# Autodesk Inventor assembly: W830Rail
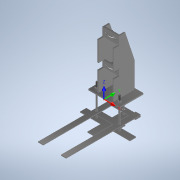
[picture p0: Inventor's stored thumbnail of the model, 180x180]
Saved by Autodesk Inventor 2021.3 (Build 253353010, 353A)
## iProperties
Created: 2019-06
Part Number: W830Rail
Document SubType Name: Assembly
Designer: u1426
Author: u1426
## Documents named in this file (10)
- S:\Projects\Billings\4889_STPP-14-3-17-78_WHEATLND-CO-L-EAST\BR\CSK_CADD-SKETCHES\Inventor_TJB\Parts\W830Post-Slab.iam
- S:\Projects\Billings\4889_STPP-14-3-17-78_WHEATLND-CO-L-EAST\BR\CSK_CADD-SKETCHES\Inventor_TJB\Parts\Post.ipt
- S:\Projects\Billings\4889_STPP-14-3-17-78_WHEATLND-CO-L-EAST\BR\CSK_CADD-SKETCHES\Inventor_TJB\Parts\ANSI B18.2.1 - 3_4-10 UNC - 1.25(4).ipt
- S:\Projects\Billings\4889_STPP-14-3-17-78_WHEATLND-CO-L-EAST\BR\CSK_CADD-SKETCHES\Inventor_TJB\Parts\ANSI B18.22.1 - 3_4 - wide - Type A.ipt
- S:\Projects\Billings\4889_STPP-14-3-17-78_WHEATLND-CO-L-EAST\BR\CSK_CADD-SKETCHES\Inventor_TJB\Parts\ANSI B18.2.2 - 3_4 - 10(8).ipt
- S:\Projects\Billings\4889_STPP-14-3-17-78_WHEATLND-CO-L-EAST\BR\CSK_CADD-SKETCHES\Inventor_TJB\Parts\RailBolt.ipt
- S:\Projects\Billings\4889_STPP-14-3-17-78_WHEATLND-CO-L-EAST\BR\CSK_CADD-SKETCHES\Inventor_TJB\Parts\ASME B18.21.1 - 5_8(1).ipt
- S:\Projects\Billings\4889_STPP-14-3-17-78_WHEATLND-CO-L-EAST\BR\CSK_CADD-SKETCHES\Inventor_TJB\Parts\ANSI B18.2.2 - 5_8 - 11(8).ipt
- S:\Projects\Billings\4889_STPP-14-3-17-78_WHEATLND-CO-L-EAST\BR\CSK_CADD-SKETCHES\Inventor_TJB\Parts\LowerAnchorage.ipt
- S:\Projects\Billings\4889_STPP-14-3-17-78_WHEATLND-CO-L-EAST\BR\CSK_CADD-SKETCHES\Inventor_TJB\Parts\UpperAnchorage.ipt
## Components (28 placed, 9 different names)
1. Post:1 — Flush:104, Flush:105, Flush:106, Flush:107, Flush:108, Flush:109, Flush:113, Flush:114, Flush:115, Flush:116, Mate:2, Flush:117, Mate:4, Flush:118, Mate:6, Mate:7, Mate:8, Mate:12, Mate:13, Mate:17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
2. LowerAnchorage:1 — Flush:107, Flush:108, Flush:109, Mate:1, Mate:3, Mate:5
3. UpperAnchorage:1 — Flush:104, Flush:105, Flush:106
4. Heavy Hex Bolt - Inch 3/4-10 UNC - 1.25:1 — Mate:1, Flush:116, Mate:2, Mate:9, Mate:10, Mate:11, Flush:119, Mate:24, Flush:122, Mate:25, Mate:26
5. Heavy Hex Bolt - Inch 3/4-10 UNC - 1.25:2 — Mate:3, Flush:117, Mate:4, Mate:14, Mate:15, Mate:16, Flush:120, Mate:29, Mate:30, Mate:31, Flush:123
6. Heavy Hex Bolt - Inch 3/4-10 UNC - 1.25:3 — Mate:5, Flush:118, Mate:6, Mate:19, Mate:20, Mate:21, Flush:121, Mate:34, Mate:35, Mate:36, Flush:124
7. Plain Washer (Inch) 3/4 - wide - Type A:1 — Mate:7, Mate:9, Mate:10, Mate:22
8. Plain Washer (Inch) 3/4 - wide - Type A:2 — Mate:8, Mate:11, Flush:119, Mate:23
9. Plain Washer (Inch) 3/4 - wide - Type A:3 — Mate:12, Mate:14, Mate:15, Mate:27
10. Plain Washer (Inch) 3/4 - wide - Type A:4 — Mate:13, Mate:16, Flush:120, Mate:28
11. Plain Washer (Inch) 3/4 - wide - Type A:5 — Mate:17, Mate:19, Mate:20, Mate:32
12. Plain Washer (Inch) 3/4 - wide - Type A:6 — Mate:18, Mate:21, Flush:121, Mate:33
13. Heavy Hex Nut - Inch 3/4 - 10:1 — Mate:22, Mate:24, Flush:122
14. Heavy Hex Nut - Inch 3/4 - 10:2 — Mate:23, Mate:25, Mate:26
15. Heavy Hex Nut - Inch 3/4 - 10:3 — Mate:27, Mate:29, Mate:30
16. Heavy Hex Nut - Inch 3/4 - 10:4 — Mate:28, Mate:31, Flush:123
17. Heavy Hex Nut - Inch 3/4 - 10:5 — Mate:32, Mate:34, Mate:35
18. Heavy Hex Nut - Inch 3/4 - 10:6 — Mate:33, Mate:36, Flush:124
19. RailBolt:1 — Mate:37, Mate:39, Flush:125, Mate:41, Mate:42, Mate:45, Flush:127, Mate:46, Flush:128, Mate:53, Flush:131, Mate:54, Flush:132
20. RailBolt:2 — Mate:38, Mate:40, Flush:126, Mate:43, Mate:44, Mate:47, Flush:129, Mate:48, Flush:130, Mate:55, Flush:133, Mate:56, Flush:134
21. Heavy Helical Spring Lock Washer (Inch) 5/8:1 — Mate:41, Mate:45, Flush:127, Mate:49
22. Heavy Helical Spring Lock Washer (Inch) 5/8:2 — Mate:42, Mate:46, Flush:128, Mate:50
23. Heavy Helical Spring Lock Washer (Inch) 5/8:3 — Mate:43, Mate:47, Flush:129, Mate:51
24. Heavy Helical Spring Lock Washer (Inch) 5/8:4 — Mate:44, Mate:48, Flush:130, Mate:52
25. Heavy Hex Nut - Inch 5/8 - 11:1 — Mate:49, Mate:53, Flush:131
26. Heavy Hex Nut - Inch 5/8 - 11:2 — Mate:50, Mate:54, Flush:132
27. Heavy Hex Nut - Inch 5/8 - 11:3 — Mate:51, Mate:55, Flush:133
28. Heavy Hex Nut - Inch 5/8 - 11:4 — Mate:52, Mate:56, Flush:134
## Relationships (84: Mate 56, Flush 28)
- Flush:104: Post:1 ↔ UpperAnchorage:1
- Flush:105: Post:1 ↔ UpperAnchorage:1
- Flush:106: Post:1 ↔ UpperAnchorage:1
- Flush:107: Post:1 ↔ LowerAnchorage:1
- Flush:108: Post:1 ↔ LowerAnchorage:1
- Flush:109: Post:1 ↔ LowerAnchorage:1
- Flush:113: Post:1
- Flush:114: Post:1
- Flush:115: Post:1
- Mate:1: LowerAnchorage:1 ↔ Heavy Hex Bolt - Inch 3/4-10 UNC - 1.25:1
- Flush:116: Post:1 ↔ Heavy Hex Bolt - Inch 3/4-10 UNC - 1.25:1
- Mate:2: Post:1 ↔ Heavy Hex Bolt - Inch 3/4-10 UNC - 1.25:1
- Mate:3: LowerAnchorage:1 ↔ Heavy Hex Bolt - Inch 3/4-10 UNC - 1.25:2
- Flush:117: Post:1 ↔ Heavy Hex Bolt - Inch 3/4-10 UNC - 1.25:2
- Mate:4: Post:1 ↔ Heavy Hex Bolt - Inch 3/4-10 UNC - 1.25:2
- Mate:5: LowerAnchorage:1 ↔ Heavy Hex Bolt - Inch 3/4-10 UNC - 1.25:3
- Flush:118: Post:1 ↔ Heavy Hex Bolt - Inch 3/4-10 UNC - 1.25:3
- Mate:6: Post:1 ↔ Heavy Hex Bolt - Inch 3/4-10 UNC - 1.25:3
- Mate:7: Post:1 ↔ Plain Washer (Inch) 3/4 - wide - Type A:1
- Mate:8: Post:1 ↔ Plain Washer (Inch) 3/4 - wide - Type A:2
- Mate:9: Heavy Hex Bolt - Inch 3/4-10 UNC - 1.25:1 ↔ Plain Washer (Inch) 3/4 - wide - Type A:1
- Mate:10: Heavy Hex Bolt - Inch 3/4-10 UNC - 1.25:1 ↔ Plain Washer (Inch) 3/4 - wide - Type A:1
- Mate:11: Heavy Hex Bolt - Inch 3/4-10 UNC - 1.25:1 ↔ Plain Washer (Inch) 3/4 - wide - Type A:2
- Flush:119: Heavy Hex Bolt - Inch 3/4-10 UNC - 1.25:1 ↔ Plain Washer (Inch) 3/4 - wide - Type A:2
- Mate:12: Post:1 ↔ Plain Washer (Inch) 3/4 - wide - Type A:3
- Mate:13: Post:1 ↔ Plain Washer (Inch) 3/4 - wide - Type A:4
- Mate:14: Heavy Hex Bolt - Inch 3/4-10 UNC - 1.25:2 ↔ Plain Washer (Inch) 3/4 - wide - Type A:3
- Mate:15: Heavy Hex Bolt - Inch 3/4-10 UNC - 1.25:2 ↔ Plain Washer (Inch) 3/4 - wide - Type A:3
- Mate:16: Heavy Hex Bolt - Inch 3/4-10 UNC - 1.25:2 ↔ Plain Washer (Inch) 3/4 - wide - Type A:4
- Flush:120: Heavy Hex Bolt - Inch 3/4-10 UNC - 1.25:2 ↔ Plain Washer (Inch) 3/4 - wide - Type A:4
- Mate:17: Post:1 ↔ Plain Washer (Inch) 3/4 - wide - Type A:5
- Mate:18: Post:1 ↔ Plain Washer (Inch) 3/4 - wide - Type A:6
- Mate:19: Heavy Hex Bolt - Inch 3/4-10 UNC - 1.25:3 ↔ Plain Washer (Inch) 3/4 - wide - Type A:5
- Mate:20: Heavy Hex Bolt - Inch 3/4-10 UNC - 1.25:3 ↔ Plain Washer (Inch) 3/4 - wide - Type A:5
- Mate:21: Heavy Hex Bolt - Inch 3/4-10 UNC - 1.25:3 ↔ Plain Washer (Inch) 3/4 - wide - Type A:6
- Flush:121: Heavy Hex Bolt - Inch 3/4-10 UNC - 1.25:3 ↔ Plain Washer (Inch) 3/4 - wide - Type A:6
- Mate:22: Plain Washer (Inch) 3/4 - wide - Type A:1 ↔ Heavy Hex Nut - Inch 3/4 - 10:1
- Mate:23: Plain Washer (Inch) 3/4 - wide - Type A:2 ↔ Heavy Hex Nut - Inch 3/4 - 10:2
- Mate:24: Heavy Hex Bolt - Inch 3/4-10 UNC - 1.25:1 ↔ Heavy Hex Nut - Inch 3/4 - 10:1
- Flush:122: Heavy Hex Bolt - Inch 3/4-10 UNC - 1.25:1 ↔ Heavy Hex Nut - Inch 3/4 - 10:1
- Mate:25: Heavy Hex Bolt - Inch 3/4-10 UNC - 1.25:1 ↔ Heavy Hex Nut - Inch 3/4 - 10:2
- Mate:26: Heavy Hex Bolt - Inch 3/4-10 UNC - 1.25:1 ↔ Heavy Hex Nut - Inch 3/4 - 10:2
- Mate:27: Plain Washer (Inch) 3/4 - wide - Type A:3 ↔ Heavy Hex Nut - Inch 3/4 - 10:3
- Mate:28: Plain Washer (Inch) 3/4 - wide - Type A:4 ↔ Heavy Hex Nut - Inch 3/4 - 10:4
- Mate:29: Heavy Hex Bolt - Inch 3/4-10 UNC - 1.25:2 ↔ Heavy Hex Nut - Inch 3/4 - 10:3
- Mate:30: Heavy Hex Bolt - Inch 3/4-10 UNC - 1.25:2 ↔ Heavy Hex Nut - Inch 3/4 - 10:3
- Mate:31: Heavy Hex Bolt - Inch 3/4-10 UNC - 1.25:2 ↔ Heavy Hex Nut - Inch 3/4 - 10:4
- Flush:123: Heavy Hex Bolt - Inch 3/4-10 UNC - 1.25:2 ↔ Heavy Hex Nut - Inch 3/4 - 10:4
- Mate:32: Plain Washer (Inch) 3/4 - wide - Type A:5 ↔ Heavy Hex Nut - Inch 3/4 - 10:5
- Mate:33: Plain Washer (Inch) 3/4 - wide - Type A:6 ↔ Heavy Hex Nut - Inch 3/4 - 10:6
- Mate:34: Heavy Hex Bolt - Inch 3/4-10 UNC - 1.25:3 ↔ Heavy Hex Nut - Inch 3/4 - 10:5
- Mate:35: Heavy Hex Bolt - Inch 3/4-10 UNC - 1.25:3 ↔ Heavy Hex Nut - Inch 3/4 - 10:5
- Mate:36: Heavy Hex Bolt - Inch 3/4-10 UNC - 1.25:3 ↔ Heavy Hex Nut - Inch 3/4 - 10:6
- Flush:124: Heavy Hex Bolt - Inch 3/4-10 UNC - 1.25:3 ↔ Heavy Hex Nut - Inch 3/4 - 10:6
- Mate:37: Post:1 ↔ RailBolt:1
- Mate:38: Post:1 ↔ RailBolt:2
- Mate:39: Post:1 ↔ RailBolt:1
- Flush:125: Post:1 ↔ RailBolt:1
- Mate:40: Post:1 ↔ RailBolt:2
- Flush:126: Post:1 ↔ RailBolt:2
- Mate:41: RailBolt:1 ↔ Heavy Helical Spring Lock Washer (Inch) 5/8:1
- Mate:42: RailBolt:1 ↔ Heavy Helical Spring Lock Washer (Inch) 5/8:2
- Mate:43: RailBolt:2 ↔ Heavy Helical Spring Lock Washer (Inch) 5/8:3
- Mate:44: RailBolt:2 ↔ Heavy Helical Spring Lock Washer (Inch) 5/8:4
- Mate:45: RailBolt:1 ↔ Heavy Helical Spring Lock Washer (Inch) 5/8:1
- Flush:127: RailBolt:1 ↔ Heavy Helical Spring Lock Washer (Inch) 5/8:1
- Mate:46: RailBolt:1 ↔ Heavy Helical Spring Lock Washer (Inch) 5/8:2
- Flush:128: RailBolt:1 ↔ Heavy Helical Spring Lock Washer (Inch) 5/8:2
- Mate:47: RailBolt:2 ↔ Heavy Helical Spring Lock Washer (Inch) 5/8:3
- Flush:129: RailBolt:2 ↔ Heavy Helical Spring Lock Washer (Inch) 5/8:3
- Mate:48: RailBolt:2 ↔ Heavy Helical Spring Lock Washer (Inch) 5/8:4
- Flush:130: RailBolt:2 ↔ Heavy Helical Spring Lock Washer (Inch) 5/8:4
- Mate:49: Heavy Helical Spring Lock Washer (Inch) 5/8:1 ↔ Heavy Hex Nut - Inch 5/8 - 11:1
- Mate:50: Heavy Helical Spring Lock Washer (Inch) 5/8:2 ↔ Heavy Hex Nut - Inch 5/8 - 11:2
- Mate:51: Heavy Helical Spring Lock Washer (Inch) 5/8:3 ↔ Heavy Hex Nut - Inch 5/8 - 11:3
- Mate:52: Heavy Helical Spring Lock Washer (Inch) 5/8:4 ↔ Heavy Hex Nut - Inch 5/8 - 11:4
- Mate:53: RailBolt:1 ↔ Heavy Hex Nut - Inch 5/8 - 11:1
- Flush:131: RailBolt:1 ↔ Heavy Hex Nut - Inch 5/8 - 11:1
- Mate:54: RailBolt:1 ↔ Heavy Hex Nut - Inch 5/8 - 11:2
- Flush:132: RailBolt:1 ↔ Heavy Hex Nut - Inch 5/8 - 11:2
- Mate:55: RailBolt:2 ↔ Heavy Hex Nut - Inch 5/8 - 11:3
- Flush:133: RailBolt:2 ↔ Heavy Hex Nut - Inch 5/8 - 11:3
- Mate:56: RailBolt:2 ↔ Heavy Hex Nut - Inch 5/8 - 11:4
- Flush:134: RailBolt:2 ↔ Heavy Hex Nut - Inch 5/8 - 11:4
